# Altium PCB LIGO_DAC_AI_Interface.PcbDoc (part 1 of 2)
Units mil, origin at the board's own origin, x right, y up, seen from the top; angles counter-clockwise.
Board outline 2600 x 10000 mil, 6 copper layers (Top Layer, InternalPlane1, Mid-Layer 1, Mid-Layer 2, Internal Plane 2, Bottom Layer); 72 components, 113 nets, 425 pads, 169 vias.
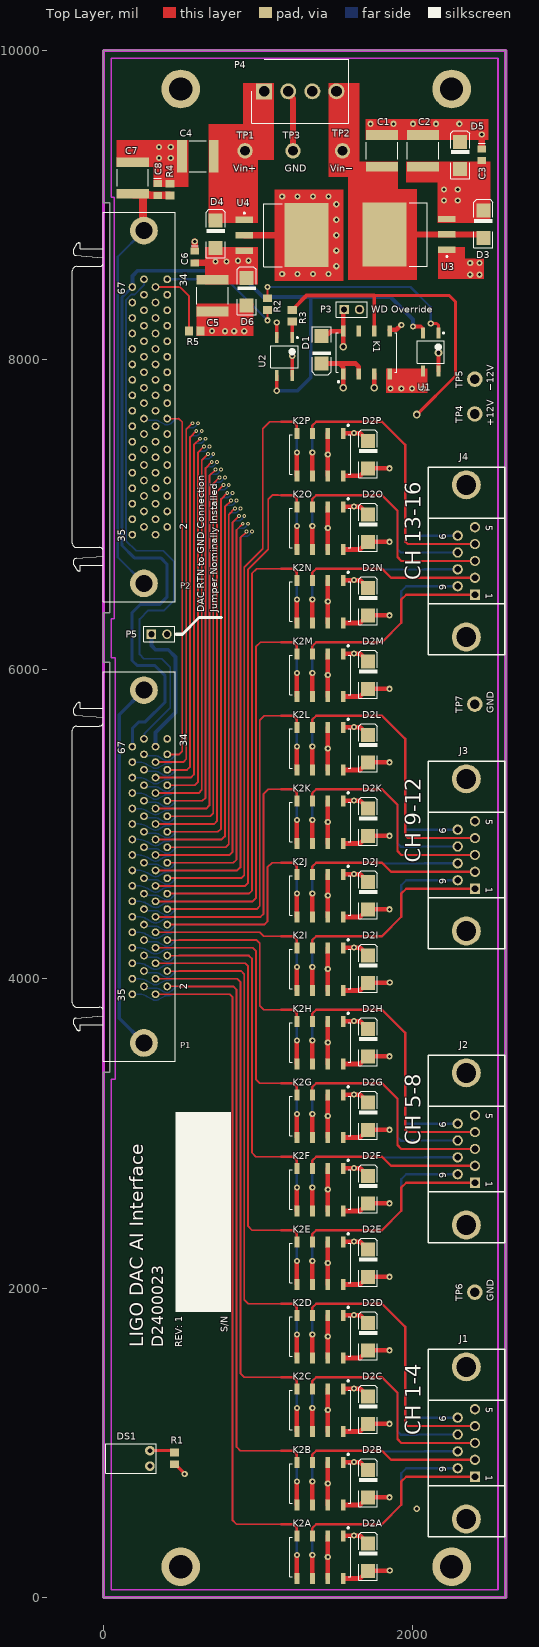
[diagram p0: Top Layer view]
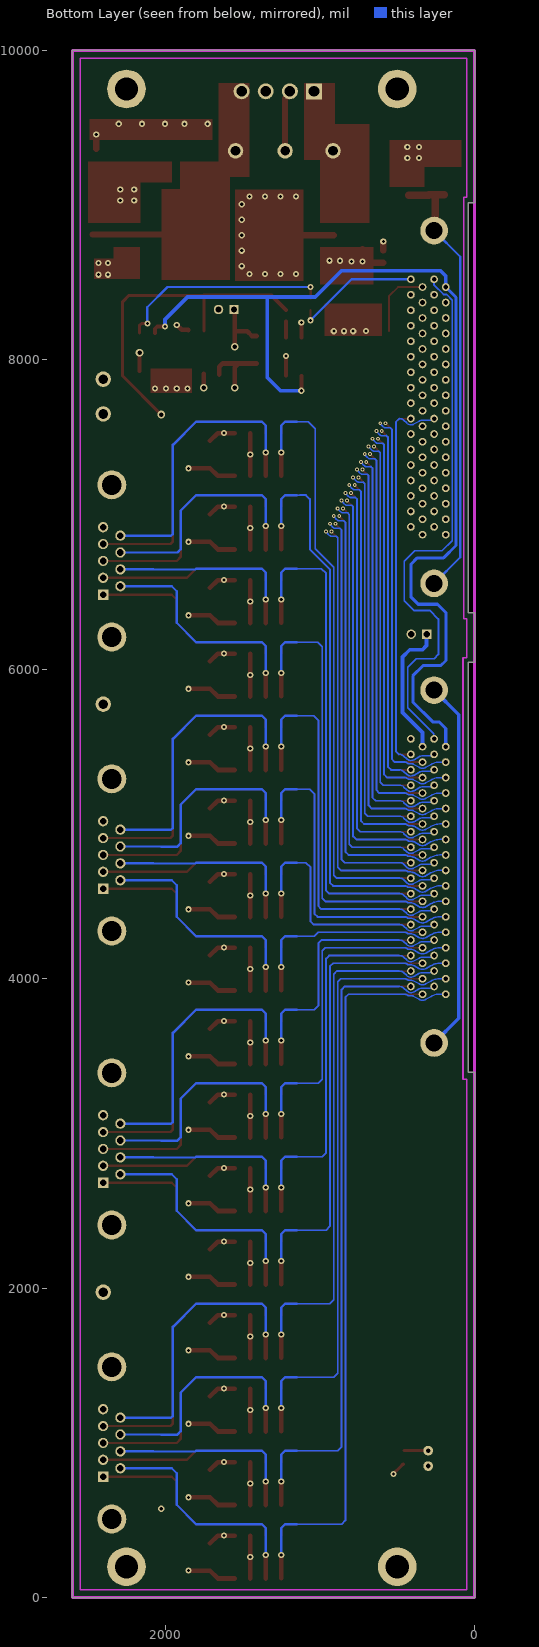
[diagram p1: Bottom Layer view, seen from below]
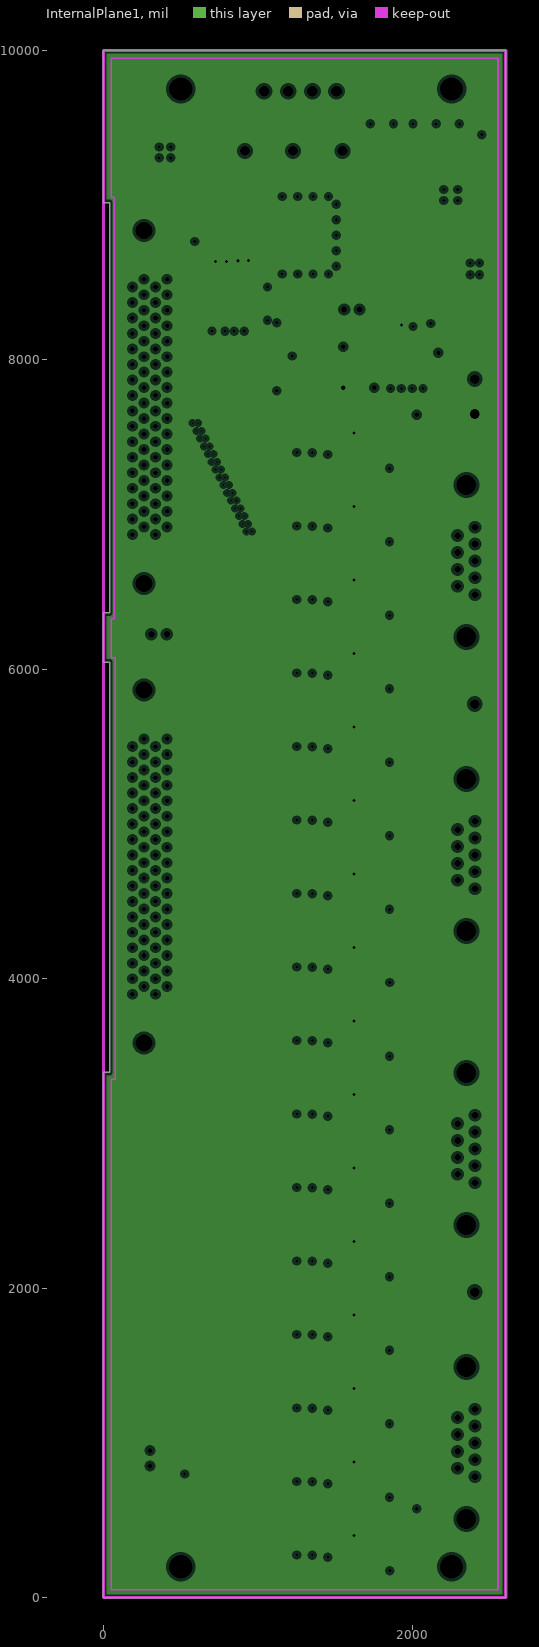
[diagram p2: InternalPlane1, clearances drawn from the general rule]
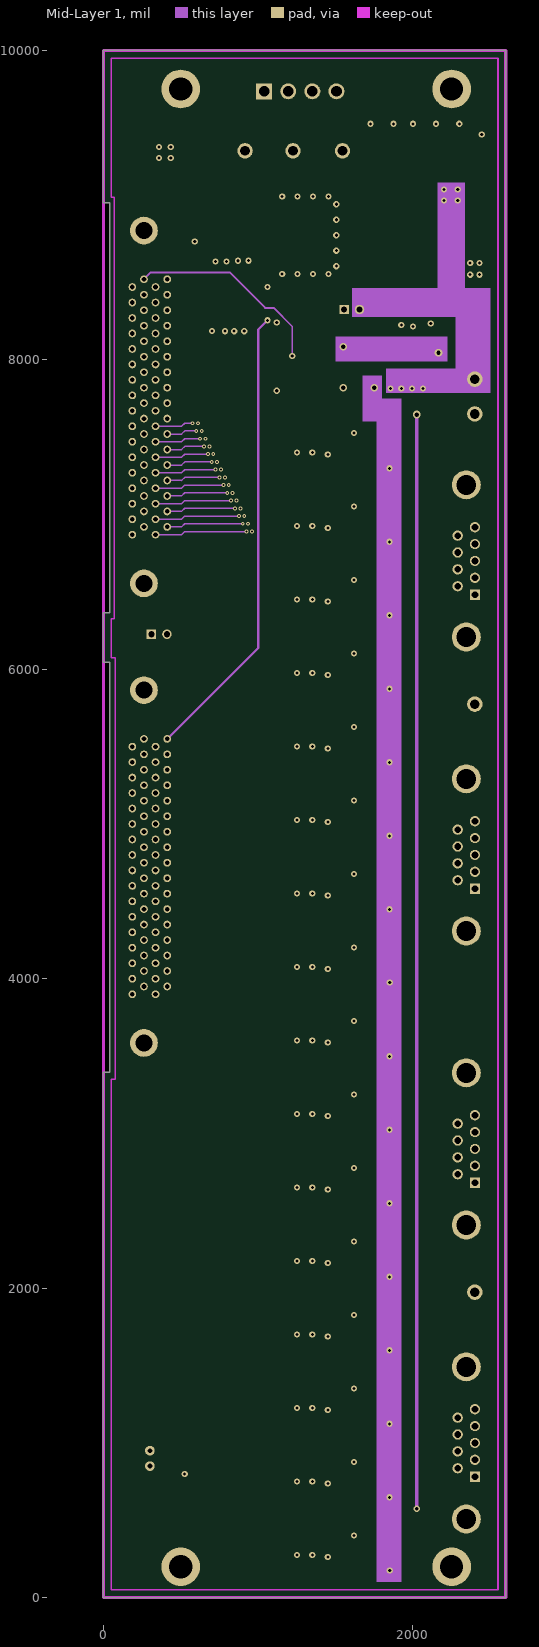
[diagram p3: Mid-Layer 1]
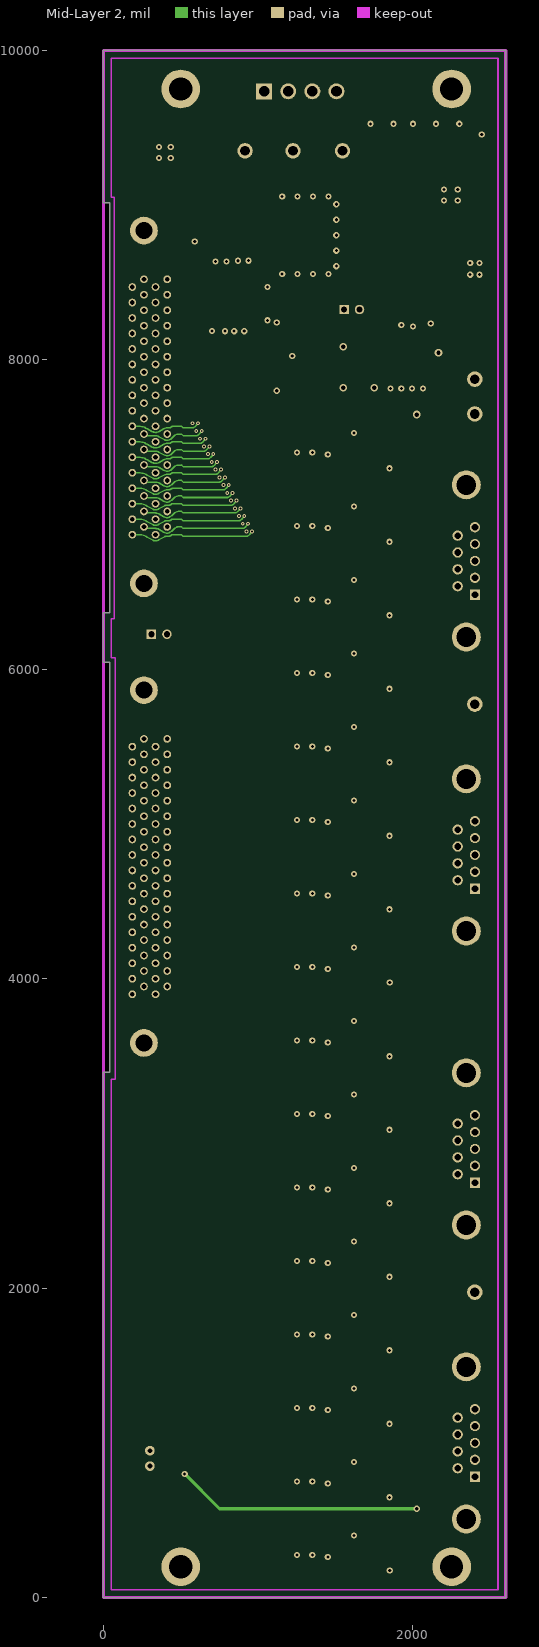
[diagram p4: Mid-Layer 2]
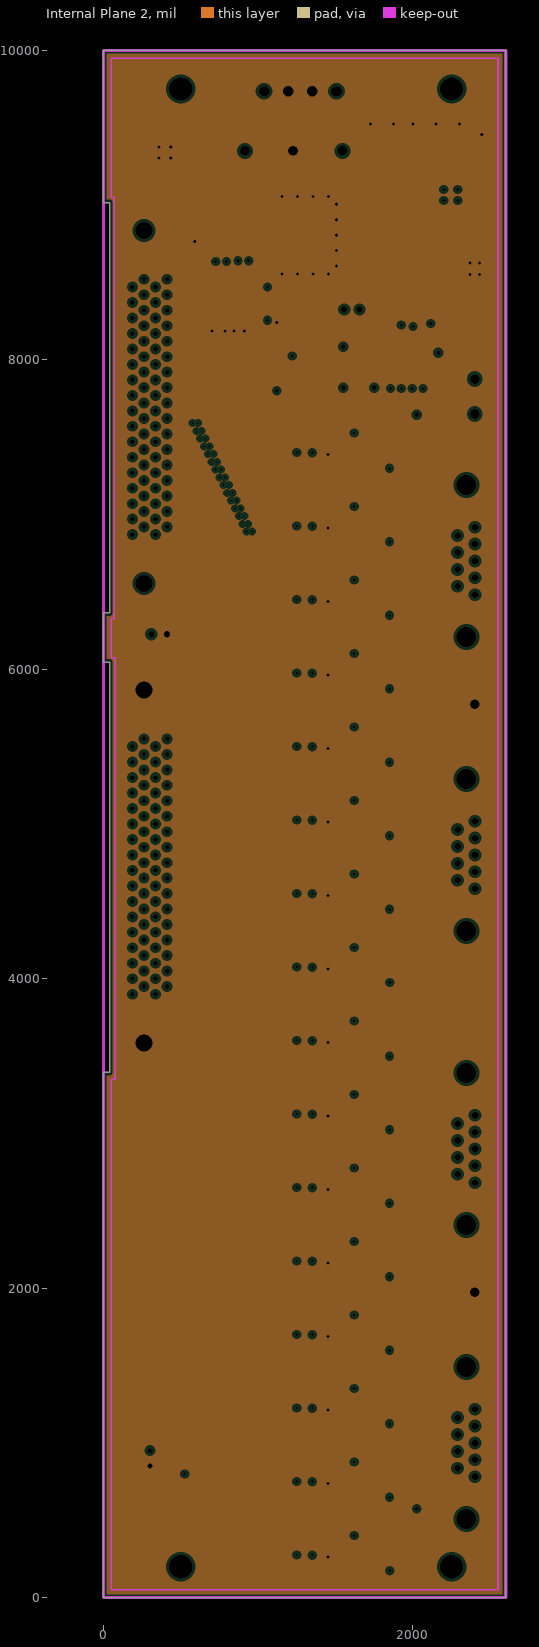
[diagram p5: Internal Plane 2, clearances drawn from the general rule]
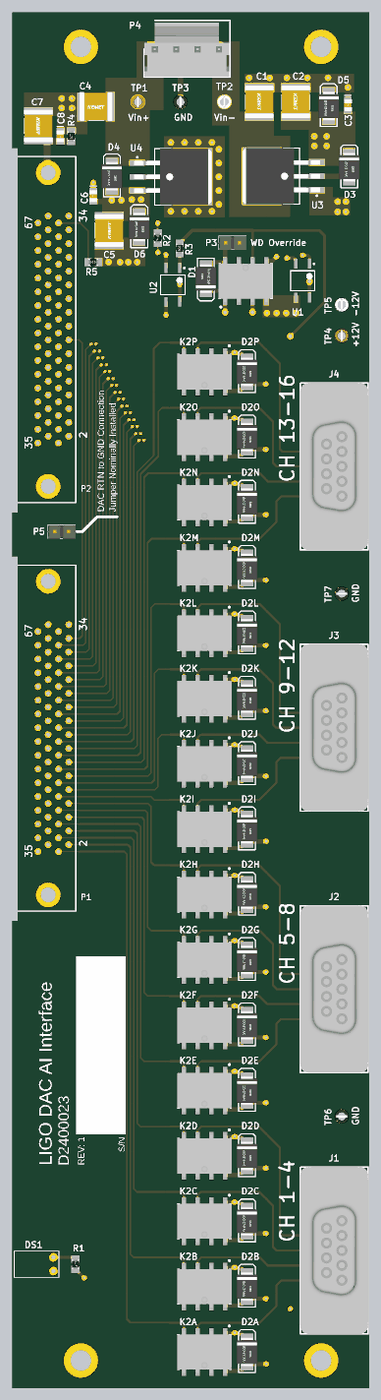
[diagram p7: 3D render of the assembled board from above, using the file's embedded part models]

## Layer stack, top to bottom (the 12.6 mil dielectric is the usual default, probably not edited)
Top Solder: solder mask 0.4, Solder Resist, Dk 3.5
Top Layer: signal copper 1.4
Dielectric1: core 12.6, FR-4, Dk 4.8
InternalPlane1: plane copper 1.4, net V+
Dielectric4: prepreg 12.6, FR-4, Dk 4.8
Mid-Layer 1: signal copper 1.4
Dielectric2: core 12.6, FR-4, Dk 4.8
Mid-Layer 2: signal copper 1.4
Dielectric3: prepreg 12.6, FR-4, Dk 4.8
Internal Plane 2: plane copper 1.4, net GND
Dielectric5: core 12.6, FR-4, Dk 4.8
Bottom Layer: signal copper 1.4
Bottom Solder: solder mask 0.4, Solder Resist, Dk 3.5

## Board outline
0,0 0,3395 40,3395 40,6045 0,6045 0,6365 40,6365 40,9015 0,9015 0,10000 2600,10000 2600,0

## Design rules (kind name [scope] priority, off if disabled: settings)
Clearance [All] p1: gap=10 ignorepadtopadclearanceinfootprint=FALSE
ComponentClearance ComponentClearance_1 [InComponent('P1')] p1: gap=0 collisioncheckmode=3 verticalgap=0 showdistances=FALSE
ComponentClearance ComponentClearance_2 [InComponent('P2')] p2: gap=0 collisioncheckmode=3 verticalgap=0 showdistances=FALSE
ComponentClearance ComponentClearance_3 [InComponent('DS1')] p3: gap=0 collisioncheckmode=3 verticalgap=0 showdistances=FALSE
ComponentClearance [All] p4: gap=10 collisioncheckmode=3 verticalgap=10 showdistances=FALSE
HoleSize [All] p1: absolutevalues=TRUE maxlimit=250 minlimit=12 maxpercent=80.000 minpercent=20.000
MinimumAnnularRing [All] p1: minimumring=6.5
PlaneClearance [All] p1: clearance=20
PlaneConnect [All] p1: planeconnectstyle=Relief reliefexpansion=20 reliefentries=4 reliefconductorwidth=10 reliefairgap=10
PolygonConnect [All] p1: connectstyle=Relief reliefconductorwidth=10 reliefentries=4 polygonreliefangle="90 Angle" airgapwidth=10
RoomDefinition Relay1 [InComponentClass('Relay1')] p1: confinementstyle=ConfineIn formatcopy=FALSE lockcomponents=FALSE outline 1150,50 1800,50 1800,525 1150,525
RoomDefinition Relay2 [InComponentClass('Relay2')] p2: confinementstyle=ConfineIn formatcopy=TRUE lockcomponents=FALSE outline 1150,525 1800,525 1800,1000 1150,1000
RoomDefinition Relay3 [InComponentClass('Relay3')] p3: confinementstyle=ConfineIn formatcopy=TRUE lockcomponents=FALSE outline 1150,1000 1800,1000 1800,1475 1150,1475
RoomDefinition Relay4 [InComponentClass('Relay4')] p4: confinementstyle=ConfineIn formatcopy=TRUE lockcomponents=FALSE outline 1150,1475 1800,1475 1800,1950 1150,1950
RoomDefinition Relay5 [InComponentClass('Relay5')] p5: confinementstyle=ConfineIn formatcopy=TRUE lockcomponents=FALSE outline 1150,1950 1800,1950 1800,2425 1150,2425
RoomDefinition Relay6 [InComponentClass('Relay6')] p6: confinementstyle=ConfineIn formatcopy=TRUE lockcomponents=FALSE outline 1150,2425 1800,2425 1800,2900 1150,2900
RoomDefinition Relay7 [InComponentClass('Relay7')] p7: confinementstyle=ConfineIn formatcopy=TRUE lockcomponents=FALSE outline 1150,2900 1800,2900 1800,3375 1150,3375
RoomDefinition Relay8 [InComponentClass('Relay8')] p8: confinementstyle=ConfineIn formatcopy=TRUE lockcomponents=FALSE outline 1150,3375 1800,3375 1800,3850 1150,3850
RoomDefinition Relay9 [InComponentClass('Relay9')] p9: confinementstyle=ConfineIn formatcopy=TRUE lockcomponents=FALSE outline 1150,3850 1800,3850 1800,4325 1150,4325
RoomDefinition Relay10 [InComponentClass('Relay10')] p10: confinementstyle=ConfineIn formatcopy=TRUE lockcomponents=FALSE outline 1150,4325 1800,4325 1800,4800 1150,4800
RoomDefinition Relay11 [InComponentClass('Relay11')] p11: confinementstyle=ConfineIn formatcopy=TRUE lockcomponents=FALSE outline 1150,4800 1800,4800 1800,5275 1150,5275
RoomDefinition Relay12 [InComponentClass('Relay12')] p12: confinementstyle=ConfineIn formatcopy=TRUE lockcomponents=FALSE outline 1150,5275 1800,5275 1800,5750 1150,5750
RoomDefinition Relay13 [InComponentClass('Relay13')] p13: confinementstyle=ConfineIn formatcopy=TRUE lockcomponents=FALSE outline 1150,5750 1800,5750 1800,6225 1150,6225
RoomDefinition Relay14 [InComponentClass('Relay14')] p14: confinementstyle=ConfineIn formatcopy=TRUE lockcomponents=FALSE outline 1150,6225 1800,6225 1800,6700 1150,6700
RoomDefinition Relay15 [InComponentClass('Relay15')] p15: confinementstyle=ConfineIn formatcopy=TRUE lockcomponents=FALSE outline 1150,6700 1800,6700 1800,7175 1150,7175
RoomDefinition Relay16 [InComponentClass('Relay16')] p16: confinementstyle=ConfineIn formatcopy=TRUE lockcomponents=FALSE outline 1150,7175 1800,7175 1800,7650 1150,7650
RoutingVias [All] p1: holewidth=20 width=40 viastyle="Through Hole" minholewidth=12 minwidth=25 maxholewidth=28 maxwidth=50
SilkToSolderMaskClearance SilkscreenOverComponentPads [IsPad] p1: minsilkscreentomaskgap=5 clearancetoexposedcopper=TRUE
SolderMaskExpansion SolderMaskExpansion_1 [IsVia And (HoleDiameter = 12)] p1: expansion=5 istentingtop=FALSE
SolderMaskExpansion [All] p2: expansion=4 istentingtop=FALSE
SupplyNets "Schematic Supply Nets_5" [InNet('V-')] p1: voltage=0.000
SupplyNets "Schematic Supply Nets_4" [InNet('DGND')] p2: voltage=0.000
SupplyNets "Schematic Supply Nets_3" [InNet('Vin+')] p3: voltage=0.000
SupplyNets "Schematic Supply Nets_2" [InNet('GND')] p4: voltage=0.000
SupplyNets "Schematic Supply Nets_1" [InNet('Vin-')] p5: voltage=0.000
SupplyNets "Schematic Supply Nets" [InNet('V+')] p6: voltage=0.000
Width [All] p1: maxlimit=100 minlimit=8 preferedwidth=12
25 further rules are at their usual default settings.

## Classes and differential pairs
net class OutputP[1..16]: OutputP1 OutputP2 OutputP3 OutputP4 OutputP5 OutputP6 OutputP7 OutputP8 OutputP9 OutputP10 OutputP11 OutputP12 OutputP13 OutputP14 OutputP15 OutputP16
net class OutputN[1..16]: OutputN1 OutputN2 OutputN3 OutputN4 OutputN5 OutputN6 OutputN7 OutputN8 OutputN9 OutputN10 OutputN11 OutputN12 OutputN13 OutputN14 OutputN15 OutputN16
channel class LIGO_DAC_AI_Interface2: Relay1 Relay2 Relay3 Relay4 Relay5 Relay6 Relay7 Relay8 Relay9 Relay10 Relay11 Relay12 Relay13 Relay14 Relay15 Relay16
net class INPUTP[1..16]: InputP1 InputP2 InputP3 InputP4 InputP5 InputP6 InputP7 InputP8 InputP9 InputP10 InputP11 InputP12 InputP13 INPUTP14 InputP15 InputP16
net class INPUTN[1..16]: InputN1 InputN2 InputN3 InputN4 InputN5 InputN6 InputN7 InputN8 InputN9 InputN10 InputN11 InputN12 InputN13 InputN14 InputN15 InputN16
component class Relay16: D2P K2P
component class Relay15: D2O K2O
component class Relay14: D2N K2N
component class Relay13: D2M K2M
component class Relay12: D2L K2L
component class Relay11: D2K K2K
component class Relay10: D2J K2J
component class Relay9: D2I K2I
component class Relay8: D2H K2H
component class Relay7: D2G K2G
component class Relay6: D2F K2F
component class Relay5: D2E K2E
component class Relay4: D2D K2D
component class Relay3: D2C K2C
component class Relay2: D2B K2B
component class Relay1: D2A K2A
component class LIGO_DAC_AI_Interface1: C1 C2 C3 C4 C5 C6 C7 C8 D1 D3 D4 D5 D6 DS1 J1 J2 J3 J4 K1 P1 P2 P3 P4 P5 R1 R2 R3 R4 R5 R6 TP1 TP2 TP3 TP4 TP5 TP6 TP7 U1 U2 U3 U4

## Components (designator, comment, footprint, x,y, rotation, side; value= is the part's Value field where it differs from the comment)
C1 "47u" CC5650-2220 1800,9350 r270 top
C2 "47u" CC5650-2220 2065,9350 r270 top
C3 "100n" CC2013-0805 2445,9325 r270 top
C4 "47u" CC5650-2220 610,9315 r0 top
C5 "47u" CC5650-2220 705,8415 r90 top
C6 "100n" CC2013-0805 590,8665 r270 top
C7 "47u" CC5650-2220 190,9175 r270 top
C8 "100n" CC2013-0805 350,9100 r270 top
D1 "RS2G" DO-SMB 1410,8065 r270 top
D2A "RS2G" DO-SMB 1710,262.2 r90 top (schematic designator D2)
D2B "RS2G" DO-SMB 1710,737.2 r90 top (schematic designator D2)
D2C "RS2G" DO-SMB 1710,1212.2 r90 top (schematic designator D2)
D2D "RS2G" DO-SMB 1710,1687.2 r90 top (schematic designator D2)
D2E "RS2G" DO-SMB 1710,2162.2 r90 top (schematic designator D2)
D2F "RS2G" DO-SMB 1710,2637.2 r90 top (schematic designator D2)
D2G "RS2G" DO-SMB 1710,3112.2 r90 top (schematic designator D2)
D2H "RS2G" DO-SMB 1710,3587.2 r90 top (schematic designator D2)
D2I "RS2G" DO-SMB 1710,4062.2 r90 top (schematic designator D2)
D2J "RS2G" DO-SMB 1710,4537.2 r90 top (schematic designator D2)
D2K "RS2G" DO-SMB 1710,5012.2 r90 top (schematic designator D2)
D2L "RS2G" DO-SMB 1710,5487.2 r90 top (schematic designator D2)
D2M "RS2G" DO-SMB 1710,5962.2 r90 top (schematic designator D2)
D2N "RS2G" DO-SMB 1710,6437.2 r90 top (schematic designator D2)
D2O "RS2G" DO-SMB 1710,6912.2 r90 top (schematic designator D2)
D2P "RS2G" DO-SMB 1710,7387.2 r90 top (schematic designator D2)
D3 "RS2G" DO-SMB 2455,8875 r90 top
D4 "RS2G" DO-SMB 725,8810 r90 top
D5 "RS2G" DO-SMB 2305,9320 r90 top
D6 "RS2G" DO-SMB 925,8440 r90 top
DS1 "LED" LED-1 300,900 r180 top
J1 "DB9F" DB9F-ST 2345,1000 r270 top locked
J2 "DB9F" DB9F-ST 2345,2900 r270 top locked
J3 "DB9F" DB9F-ST 2345,4800 r270 top
J4 "DB9F" DB9F-ST 2345,6700 r270 top locked
K1 "G6K" RELAY_G6K-2F 1700,8047.2 r270 top
K2A "G6K" RELAY_G6K-2F 1400,262.2 r90 top (schematic designator K2)
K2B "G6K" RELAY_G6K-2F 1400,737.2 r90 top (schematic designator K2)
K2C "G6K" RELAY_G6K-2F 1400,1212.2 r90 top (schematic designator K2)
K2D "G6K" RELAY_G6K-2F 1400,1687.2 r90 top (schematic designator K2)
K2E "G6K" RELAY_G6K-2F 1400,2162.2 r90 top (schematic designator K2)
K2F "G6K" RELAY_G6K-2F 1400,2637.2 r90 top (schematic designator K2)
K2G "G6K" RELAY_G6K-2F 1400,3112.2 r90 top (schematic designator K2)
K2H "G6K" RELAY_G6K-2F 1400,3587.2 r90 top (schematic designator K2)
K2I "G6K" RELAY_G6K-2F 1400,4062.2 r90 top (schematic designator K2)
K2J "G6K" RELAY_G6K-2F 1400,4537.2 r90 top (schematic designator K2)
K2K "G6K" RELAY_G6K-2F 1400,5012.2 r90 top (schematic designator K2)
K2L "G6K" RELAY_G6K-2F 1400,5487.2 r90 top (schematic designator K2)
K2M "G6K" RELAY_G6K-2F 1400,5962.2 r90 top (schematic designator K2)
K2N "G6K" RELAY_G6K-2F 1400,6437.2 r90 top (schematic designator K2)
K2O "G6K" RELAY_G6K-2F 1400,6912.2 r90 top (schematic designator K2)
K2P "G6K" RELAY_G6K-2F 1400,7387.2 r90 top (schematic designator K2)
P1 "787082-7" 787082-7 0,4725 r90 top locked
P2 "787082-7" 787082-7 0,7695 r90 top locked
P3 "Header 2" TSW-102-XX-YY-S 1555,8325 r0 top
P4 "26-61-4040" HDRV4W155P0X396_1X4_1570X1001X1536P 1038.19,9735 r180 top
P5 "Header 2" TSW-102-XX-YY-S 310,6226.5 r0 top
R1 "2.21K" CR2012-0805 460,900 r270 top
R2 "499" CR2012-0805 1060,8360 r90 top
R3 "2.21K" CR2012-0805 1220,8285 r90 top
R4 "NL" CR2012-0805 430,9100 r90 top
R5 "NL" CR2012-0805 590,8185 r0 top
TP1 "Vin+" TP1-RED 915,9350 r0 top
TP2 "Vin−" TP1-WHT 1545,9350 r0 top
TP3 "GND" TP1-BLK 1225,9350 r0 top
TP4 "+12V" TP1-RED 2400,7650 r180 top
TP5 "−12V" TP1-WHT 2400,7875 r180 top
TP6 "GND" TP1-BLK 2400,1975 r270 top
TP7 "GND" TP1-BLK 2400,5775 r270 top
U1 "PS2702-1-F3-A" PS2701A-1 2115,8050 r270 top
U2 "PS2702-1-F3-A" PS2701A-1 1170,8020 r270 top
U3 "LM2990SX-12/NOPB" KTT0003B_N 1975,8810 r180 top
U4 "LM2940CSX-12/NOPB" KTT0003B_N 1155,8805 r0 top

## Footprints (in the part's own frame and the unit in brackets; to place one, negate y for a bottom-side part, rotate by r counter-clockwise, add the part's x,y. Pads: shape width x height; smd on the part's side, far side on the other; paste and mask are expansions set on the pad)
787082-7 [mm] "Connector; D Subminiature 050 Series; 68 Position; Right Angle"
  round 1.27 hole 0.762: 1(-20.955,-8.555) 2(-19.685,-10.46) 3(-18.415,-8.555) 4(-17.145,-10.46) 5(-15.875,-8.555) 6(-14.605,-10.46) 7(-13.335,-8.555) 8(-12.065,-10.46) 9(-10.795,-8.555) 10(-9.525,-10.46) 11(-8.255,-8.555) 12(-6.985,-10.46) 13(-5.715,-8.555) 14(-4.445,-10.46) 15(-3.175,-8.555) 16(-1.905,-10.46) 17(-0.635,-8.555) 18(0.635,-10.46) 19(1.905,-8.555) 20(3.175,-10.46) 21(4.445,-8.555) 22(5.715,-10.46) 23(6.985,-8.555) 24(8.255,-10.46) 25(9.525,-8.555) 26(10.795,-10.46) 27(12.065,-8.555) 28(13.335,-10.46) 29(14.605,-8.555) 30(15.875,-10.46) 31(17.145,-8.555) 32(18.415,-10.46) 33(19.685,-8.555) 34(20.955,-10.46) 35(-20.955,-4.745) 36(-19.685,-6.65) 37(-18.415,-4.745) 38(-17.145,-6.65) 39(-15.875,-4.745) 40(-14.605,-6.65) 41(-13.335,-4.745) 42(-12.065,-6.65) 43(-10.795,-4.745) 44(-9.525,-6.65) 45(-8.255,-4.745) 46(-6.985,-6.65) 47(-5.715,-4.745) 48(-4.445,-6.65) 49(-3.175,-4.745) 50(-1.905,-6.65) 51(-0.635,-4.745) 52(0.635,-6.65) 53(1.905,-4.745) 54(3.175,-6.65) 55(4.445,-4.745) 56(5.715,-6.65) 57(6.985,-4.745) 58(8.255,-6.65) 59(9.525,-4.745) 60(10.795,-6.65) 61(12.065,-4.745) 62(13.335,-6.65) 63(14.605,-4.745) 64(15.875,-6.65) 65(17.145,-4.745) 66(18.415,-6.65) 67(19.685,-4.745) 68(20.955,-6.65)
  round 4.55 hole 2.77: 69(-28.955,-6.65) 70(28.955,-6.65)
  silkscreen extent -31.95,-11.76 31.95,5.11
CC2013-0805 [mm] "Chip Capacitor; Body 2.0 x 1.3 mm (LxW typ)"
  rect 1.15x1.4 smd: 1(-0.975,0) 2(0.975,0)
  silkscreen extent -1.85,-0.6 -1.85,0.6, body extent -1.1,-0.72 1.1,0.73, height 0.88
CC5650-2220 [mm] "Chip Capacitor, Body 5.6 x 5.0mm (LxW typ)"
  rect 1.6x5.3 smd: 1(-2.6,0) 2(2.6,0)
  silkscreen extent -1.4,-2.55 1.4,2.55, body extent -3.05,-2.7 3.05,2.7, height 1.8
CR2012-0805 [mm] "Chip Resistor; Body 2.0 x 1.3 mm (LxW typ)"
  rect 1.3x1.5 smd: 1(-0.95,0) 2(0.95,0)
  body extent -1,-0.62 1,0.63, height 0.46
DB9F-ST [mm] "Receptiacle; D Subminiature 9 Position; Straight"
  rect 1.69x1.69 hole 1.09: 1(5.54,1.42)
  round 1.69 hole 1.09: 2(2.77,1.42) 3(0,1.42) 4(-2.77,1.42) 5(-5.54,1.42) 6(4.155,-1.42) 7(1.385,-1.42) 8(-1.385,-1.42) 9(-4.155,-1.42)
  round 4.76 hole 3.26: 10(12.495,0) 11(-12.495,0)
  silkscreen extent -15.4,-6.27 15.4,6.27, body extent -15.44,-6.3 15.44,6.3, height 12.32
DO-SMB [mm] "DO-214-AA/SMB; 2 C-Bend Leads; Body 5.3 x 3.6 mm, inc. leads (LxW)"
  rect 2.3x2.3 smd: 1(-2.25,0) 2(2.25,0)
  silkscreen extent -3.8,-1.55 4.1,1.55, body extent -2.75,-1.95 2.75,1.95, height 2.45
HDRV4W155P0X396_1X4_1570X1001X1536P [mm]
  rect 2.625x2.625 hole 1.75: 1(0,0)
  round 2.625 hole 1.75: 2(-3.96,0) 3(-7.92,0) 4(-11.88,0)
  silkscreen extent -13.91,-5.26 2.03,5.26, body extent -13.79,-4.83 1.91,5.17, height 14.73
KTT0003B_N [mm]
  rect 2.85x1.05 smd: 1(-6.2,2.54) 2(-6.2,0) 3(-6.2,-2.54)
  rect 7.2x10.5 smd: 4(4,0)
  silkscreen extent -6.33,-5.2 0,5.2, body extent -6.78,-5.2 7.57,5.2, height 4.64
LED-1 [mm] "Typical RED GaAs LED; 2 Leads"
  round 1.6 hole 0.8: 1(0,1.27) 2(0,-1.27)
  silkscreen extent -1.02,-2.41 7.24,2.41
PS2701A-1 [mm] "SOP, 4-Leads, Body 4.5x4.4mm (max), Pitch 2.54mm, IPC Medium Density"
  rect 1.8x0.6 smd: 1(-3.125,1.27) 2(-3.125,-1.27) 3(3.125,-1.27) 4(3.125,1.27)
  silkscreen extent -3.25,-2.25 1.83,2.25, body extent -2.2,-2.25 2.2,2.25, height 2.3
RELAY_G6K-2F [mm] "Relay"
  rect 1.8x0.8 smd: 1(3.5,-3.81) 2(3.5,-1.27) 3(3.5,1.27) 4(3.5,3.81) 5(-3.5,3.81) 6(-3.5,1.27) 7(-3.5,-1.27) 8(-3.5,-3.81)
  silkscreen extent -3.25,-5 4.94,5, body extent -3.9,-5 3.9,5, height 5.2
TP1-BLK [mm] "Testpoint pin, black"
  round 2.54 hole 1.58: 1(0,0)
  body extent -1.27,-1.27 1.27,1.27, height 4.89
TP1-RED [mm] "Testpoint pin, red"
  round 2.54 hole 1.58: 1(0,0)
  body extent -1.27,-1.27 1.27,1.27, height 4.89
TP1-WHT [mm] "Testpoint pin, white"
  round 2.54 hole 1.58: 1(0,0)
  body extent -1.27,-1.27 1.27,1.27, height 4.89
TSW-102-XX-YY-S [mm]
  rect 1.55x1.55 hole 1.02: 1(0,0)
  round 1.55 hole 1.02: 2(2.54,0)
  silkscreen extent -1.27,-1.27 3.81,1.27, body extent -1.39,-1.28 3.82,1.26, height 9.16

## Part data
C1 C2 C4 C5 C7: library part ChipCap, "Capacitor, surface mount", Part Number=445-C5750X7R1V476M230KCCT-ND, Tolerance=10%, Voltage Rating=35V
C3 C6 C8: library part ChipCap, "Capacitor, surface mount", Part Number=311-1140-1-ND, Tolerance=10%
D1 D2A D2B D2C D2D D2E D2F D2G D2H D2I D2J D2K D2L D2M D2N D2O D2P D3 D4 D5 D6: library part DIODE, "Single diode", Part Number=RS2G-E3/52TGICT-ND, Voltage Rating=400V
DS1: "Panel mount LED", Part Number=67-1304-ND
J1 J2 J3 J4: "Receptacle Assembly, 9 Position, Right Angle, .318 Series", Part Number=A34072-ND
K1 K2A K2B K2C K2D K2E K2F K2G K2H K2I K2J K2K K2L K2M K2N K2O K2P: library part Relay_DPDT_GK, "Dual-pole dual-throw relay", Coil Voltage=24V, Current Rating=2A, Part Number=Z114CT-ND
P1 P2: "Receptacle Assembly, Shielded, Right Angle, AMPLIMITE", Part Number=A31814-ND
P3 P5: "Header, 2-Pin", Part Number=SAM10844-ND
P4: "Connector", Manufacturer_Name=Molex, Part Number=WM5226-ND
R1 R3: library part ChipRes1, "Resistor, surface mount", Part Number=311-2.21KCRCT-ND, Tolerance=1%
R2: library part ChipRes1, "Resistor, surface mount", Part Number=311-499CRCT-ND, Tolerance=1%
R4 R5: library part ChipRes1, "Resistor, surface mount", Tolerance=1%
TP1 TP4: library part TP_POSITIVE, "Testpoint, red", Part Number=5005K-ND
TP2 TP5: library part TP_NEGATIVE, "Testpoint, white", Part Number=5007K-ND
TP3 TP6 TP7: library part TP_GND, "Testpoint, black", Part Number=5006K-ND
U1 U2: library part PS2701A, "High Isolation Voltage SOP Photocoupler", Part Number=559-1027-1-ND
U3: library part LM2990SX-12, "Negative Low Dropout Regulator, 3-pin TO-263", Part Number=LM2990SX-12/NOPBCT-ND
U4: library part LM2940CS-12/NOPB, "1A Low Dropout Regulator, 3-pin TO-263, Pb-Free", Part Number=LM2940CSX-12/NOPBCT-ND

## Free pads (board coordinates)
  round 250 hole 150: 0(2250,200) 1(2250,9750) 2(500,9750) 3(500,200)

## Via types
v1: diameter 40, hole 20, Top Layer to Bottom Layer, 134 vias
v2: diameter 25, hole 12, Top Layer to Bottom Layer, 30 vias
v3: diameter 50, hole 28, Top Layer to Bottom Layer, 5 vias

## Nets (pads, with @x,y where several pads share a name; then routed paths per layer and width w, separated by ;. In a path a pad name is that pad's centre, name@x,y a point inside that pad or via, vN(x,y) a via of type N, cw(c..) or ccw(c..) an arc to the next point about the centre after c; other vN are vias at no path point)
DAC1ENABLE: D2A.1 D2B.1 D2C.1 D2D.1 D2E.1 D2F.1 D2G.1 D2H.1 D2I.1 D2J.1 D2K.1 D2L.1 D2M.1 D2N.1 D2O.1 D2P.1 K1.3 K2A.8 K2B.8 K2C.8 K2D.8 K2E.8 K2F.8 K2G.8 K2H.8 K2I.8 K2J.8 K2K.8 K2L.8 K2M.8 K2N.8 K2O.8 K2P.8 | length 5195.5
  Top Layer w30: K2A.8@1550,124.41 1660.79,124.41 D2A.1@1710,173.62 1848.62,173.62 v1(1850,175) ; K2B.8@1550,599.41 1660.79,599.41 D2B.1@1710,648.62 v1(1848.62,648.62) ; K2C.8@1550,1074.41 1660.79,1074.41 D2C.1@1710,1123.62 v1(1848.62,1123.62) ; K2D.8@1550,1549.41 1660.79,1549.41 D2D.1@1710,1598.62 v1(1848.62,1598.62) ; K2E.8@1550,2024.41 1660.79,2024.41 D2E.1@1710,2073.62 v1(1848.62,2073.62) ; K2F.8@1550,2499.41 1660.79,2499.41 D2F.1@1710,2548.62 v1(1848.62,2548.62) ; K2G.8@1550,2974.41 1660.79,2974.41 D2G.1@1710,3023.62 v1(1848.62,3023.62) ; K2H.8@1550,3449.41 1660.79,3449.41 D2H.1@1710,3498.62 v1(1848.62,3498.62) ; K2I.8@1550,3924.41 1660.79,3924.41 D2I.1@1710,3973.62 v1@1848.62,3973.62 ; K2J.8@1550,4399.41 1660.79,4399.41 D2J.1@1710,4448.62 v1(1848.62,4448.62) ; K2K.8@1550,4874.41 1660.79,4874.41 D2K.1@1710,4923.62 v1(1848.62,4923.62) ; K2L.8@1550,5349.41 1660.79,5349.41 D2L.1@1710,5398.62 v1(1848.62,5398.62) ; K2M.8@1550,5824.41 1660.79,5824.41 D2M.1@1710,5873.62 v1(1848.62,5873.62) ; K2N.8@1550,6299.41 1660.79,6299.41 D2N.1@1710,6348.62 v1(1848.62,6348.62) ; K2O.8@1550,6774.41 1660.79,6774.41 D2O.1@1710,6823.62 v1(1848.62,6823.62) ; K2P.8@1550,7249.41 1660.79,7249.41 D2P.1@1710,7298.62 v1(1848.62,7298.62) ; v3(1750,7820) K1.3@1750,7909.41
  other v1: 1850,3975
DGND: P1.67 P2.67 U1.2 U2.3 | length 6695.9
  Top Layer w25: v1(1120,7800) U2.3@1120,7896.97 ; v1(2000,8215) 2050.36,8215 2065,8200.36 U1.2@2065,8173.03
  Bottom Layer w18: 120,6800 120,8403.19
  Bottom Layer w20: 120,6800 200,6720 370,6720 410,6680 410,6465 365,6420 240,6420 185,6365 185,6057 218,6024 332,6024 399,5957 399,5788 271,5660 230,5660 186.81,5616.81 P1.67@186.81,5500 ; 120,8403.19 P2.67@186.81,8470
  Bottom Layer w25: P2.67@186.81,8470 186.81,8541.81 220,8575 860,8575 1030,8405 1340,8405 ; v1(1120,7800) 1255,7800 1340,7885 1340,8405 ; v1(2000,8215) 2000,8260 1855,8405 1340,8405
GND: C1.1 C2.1 C3.1 C4.1 C5.1 C6.1 C7.1 C8.1 D5.2 D6.1 DS1.1 K2A.2 K2A.7 K2B.2 K2B.7 K2C.2 K2C.7 K2D.2 K2D.7 K2E.2 K2E.7 K2F.2 K2F.7 K2G.2 K2G.7 K2H.2 K2H.7 K2I.2 K2I.7 K2J.2 K2J.7 K2K.2 K2K.7 K2L.2 K2L.7 K2M.2 K2M.7 K2N.2 K2N.7 K2O.2 K2O.7 K2P.2 K2P.7 P1.69 P1.70 P4.2 P4.3 P5.2 R4.2 R5.2 TP3.1 TP6.1 TP7.1 U2.2 U3.1 U4.2 U4.4 | length 8010.7
  Top Layer w25: R5.2@624.4,8185.4 v1(702,8185.4) ; U2.2@1120,8143.03 v1(1120,8240)
  Top Layer w30: K2A.7@1450,124.41 v1(1450,262.2) K2A.2@1450,400 ; K2B.7@1450,599.41 v1(1450,737.2) K2B.2@1450,875 ; K2C.7@1450,1074.41 v1(1450,1212.2) K2C.2@1450,1350 ; K2D.7@1450,1549.41 v1(1450,1687.2) K2D.2@1450,1825 ; K2E.7@1450,2024.41 v1(1450,2162.2) K2E.2@1450,2300 ; K2F.7@1450,2499.41 v1(1450,2637.2) K2F.2@1450,2775 ; K2G.7@1450,2974.41 v1(1450,3112.2) K2G.2@1450,3250 ; K2H.7@1450,3449.41 v1(1450,3587.2) K2H.2@1450,3725 ; K2I.7@1450,3924.41 v1(1450,4062.2) K2I.2@1450,4200 ; K2J.7@1450,4399.41 v1(1450,4537.2) K2J.2@1450,4675 ; K2K.7@1450,4874.41 v1(1450,5012.2) K2K.2@1450,5150 ; K2L.7@1450,5349.41 v1(1450,5487.2) K2L.2@1450,5625 ; K2M.7@1450,5824.41 v1(1450,5962.2) K2M.2@1450,6100 ; K2N.7@1450,6299.41 v1(1450,6437.2) K2N.2@1450,6575 ; K2O.7@1450,6774.41 v1(1450,6912.2) K2O.2@1450,7050 ; K2P.7@1450,7249.41 v1(1450,7387.2) K2P.2@1450,7525
  Top Layer w40: C6.1@590,8706.02 v1(590,8765) ; U4.2@910.91,8805 U4.4@1312.48,8805 ; P4.2@1206,9725 1206,9705.95 1225,9686.95 TP3.1@1225,9350 TP3.1@1225,9344.27 ; C2.1@2040,9450.98 2040,9525 ; C3.1@2445,9363.39 v1(2445,9455)
  Bottom Layer w25: P1.69@261.81,3585.04 102.5,3744.35 102.5,5705.65 P1.70@261.81,5864.96
  other v1: 785,8185 845,8185 910,8185 2370,8550 2430,8550 1155,8555 1255,8555 1355,8555 1455,8555 1505,8605 2370,8625 2430,8625 1505,8705 1505,8805 1505,8905 1505,9005 1155,9055 1255,9055 1355,9055 1455,9055 360,9305 435,9305 360,9375 435,9375 1725,9525 1875,9525 2000,9525 2150,9525 2300,9525
InputN1: K2A.5 P1.35 | length 4815.4
  Top Layer w30: K2A.5@1250,125 v1(1250,275.59)
  Bottom Layer w9: P1.35@186.81,3900 224.74,3900 226.94,3900 cw(c226.94,3794.19) 283.01,3883.92 283.21,3883.81 315.61,3866.08 ccw(c336.81,3900) 336.81,3860 ccw(c336.81,3900) 358.01,3866.08 390.61,3883.92 cw(c411.81,3850) 411.81,3890 424.74,3890 ccw(c424.74,3907.07) 436.81,3895 cw(c448.88,3882.93) 448.88,3900 486.81,3900
  Bottom Layer w12: 486.81,3900 815,3900 835,3880 835,500 860,475 1130,475 1150,475
  Bottom Layer w15: 1150,475 1225,475 1250,450 v1(1250,275.59)
InputN2: K2B.5 P1.36 | length 4320
  Top Layer w30: K2B.5@1250,600 v1(1250,750.59)
  Bottom Layer w9: P1.36@261.81,3950 ccw(c285.95,3974.14) 285.95,3940 336.81,3940 cw(c336.81,3900) 358.01,3933.92 390.61,3916.08 ccw(c411.81,3950) 411.81,3910 ccw(c411.81,3950) 440.1,3921.72 440.1,3921.92 456.46,3938.28 cw(c484.74,3910) 484.74,3950 486.81,3950
  Bottom Layer w12: 486.81,3950 840,3950 860,3930 860,975 885,950 1130,950 1150,950
  Bottom Layer w15: 1150,950 1225,950 1250,925 v1(1250,750.59)
InputN3: K2C.5 P1.37 | length 3965.4
  Top Layer w30: K2C.5@1250,1075 v1(1250,1225.59)
  Bottom Layer w9: P1.37@186.81,4000 224.74,4000 226.94,4000 cw(c226.94,3894.19) 283.01,3983.92 283.21,3983.81 315.61,3966.08 ccw(c336.81,4000) 336.81,3960 ccw(c336.81,4000) 358.01,3966.08 390.61,3983.92 cw(c411.81,3950) 411.81,3990 424.74,3990 ccw(c424.74,4007.07) 436.81,3995 cw(c448.88,3982.93) 448.88,4000 486.81,4000
  Bottom Layer w12: 486.81,4000 865,4000 885,3980 885,1450 910,1425 1130,1425 1150,1425
  Bottom Layer w15: 1150,1425 1225,1425 1250,1400 v1(1250,1225.59)
InputN4: K2D.5 P1.38 | length 3470
  Top Layer w30: K2D.5@1250,1550 v1(1250,1700.59)
  Bottom Layer w9: P1.38@261.81,4050 ccw(c285.95,4074.14) 285.95,4040 336.81,4040 cw(c336.81,4000) 358.01,4033.92 390.61,4016.08 ccw(c411.81,4050) 411.81,4010 ccw(c411.81,4050) 440.1,4021.72 440.1,4021.92 456.46,4038.28 cw(c484.74,4010) 484.74,4050 486.81,4050
  Bottom Layer w12: 486.81,4050 890,4050 910,4030 910,1925 935,1900 1130,1900 1150,1900
  Bottom Layer w15: 1150,1900 1225,1900 1250,1875 v1(1250,1700.59)
InputN5: K2E.5 P1.39 | length 3115.4
  Top Layer w30: K2E.5@1250,2025 v1(1250,2175.59)
  Bottom Layer w9: P1.39@186.81,4100 224.74,4100 226.94,4100 cw(c226.94,3994.19) 283.01,4083.92 283.21,4083.81 315.61,4066.08 ccw(c336.81,4100) 336.81,4060 ccw(c336.81,4100) 358.01,4066.08 390.61,4083.92 cw(c411.81,4050) 411.81,4090 424.74,4090 ccw(c424.74,4107.07) 436.81,4095 cw(c448.88,4082.93) 448.88,4100 486.81,4100
  Bottom Layer w12: 486.81,4100 915,4100 935,4080 935,2400 960,2375 1130,2375 1150,2375
  Bottom Layer w15: 1150,2375 1225,2375 1250,2350 v1(1250,2175.59)
InputN6: K2F.5 P1.40 | length 2620
  Top Layer w30: K2F.5@1250,2500 v1(1250,2650.59)
  Bottom Layer w9: P1.40@261.81,4150 ccw(c285.95,4174.14) 285.95,4140 336.81,4140 cw(c336.81,4100) 358.01,4133.92 390.61,4116.08 ccw(c411.81,4150) 411.81,4110 ccw(c411.81,4150) 440.1,4121.72 440.1,4121.92 456.46,4138.28 cw(c484.74,4110) 484.74,4150 486.81,4150
  Bottom Layer w12: 486.81,4150 940,4150 960,4130 960,2875 985,2850 1130,2850 1150,2850
  Bottom Layer w15: 1150,2850 1225,2850 1250,2825 v1(1250,2650.59)
InputN7: K2G.5 P1.41 | length 2265.4
  Top Layer w30: K2G.5@1250,2975 v1(1250,3125.59)
  Bottom Layer w9: P1.41@186.81,4200 224.74,4200 226.94,4200 cw(c226.94,4094.19) 283.01,4183.92 283.21,4183.81 315.61,4166.08 ccw(c336.81,4200) 336.81,4160 ccw(c336.81,4200) 358.01,4166.08 390.61,4183.92 cw(c411.81,4150) 411.81,4190 424.74,4190 ccw(c424.74,4207.07) 436.81,4195 cw(c448.88,4182.93) 448.88,4200 486.81,4200
  Bottom Layer w12: 486.81,4200 965,4200 985,4180 985,3350 1010,3325 1130,3325 1150,3325
  Bottom Layer w15: 1150,3325 1225,3325 1250,3300 v1(1250,3125.59)
InputN8: K2H.5 P1.42 | length 1770
  Top Layer w30: K2H.5@1250,3450 v1(1250,3600.59)
  Bottom Layer w9: P1.42@261.81,4250 ccw(c285.95,4274.14) 285.95,4240 336.81,4240 cw(c336.81,4200) 358.01,4233.92 390.61,4216.08 ccw(c411.81,4250) 411.81,4210 ccw(c411.81,4250) 440.1,4221.72 440.1,4221.92 456.46,4238.28 cw(c484.74,4210) 484.74,4250 486.81,4250
  Bottom Layer w12: 486.81,4250 990,4250 1010,4230 1010,3825 1035,3800 1130,3800 1150,3800
  Bottom Layer w15: 1150,3800 1225,3800 1250,3775 v1(1250,3600.59)
InputN9: K2I.5 P1.43 | length 1427.2
  Top Layer w30: K2I.5@1250,3925 v1(1250,4075.59)
  Bottom Layer w9: P1.43@186.81,4300 224.74,4300 226.94,4300 cw(c226.94,4194.19) 283.01,4283.92 283.21,4283.81 315.61,4266.08 ccw(c336.81,4300) 336.81,4260 ccw(c336.81,4300) 358.01,4266.08 390.61,4283.92 cw(c411.81,4250) 411.81,4290 424.74,4290 ccw(c424.74,4307.07) 436.81,4295 cw(c448.88,4282.93) 448.88,4300 486.81,4300
  Bottom Layer w12: 486.81,4300 1010,4300 1035,4275 1130,4275 1150,4275
  Bottom Layer w15: 1150,4275 1225,4275 1250,4250 v1(1250,4075.59)
InputN10: K2J.5 P1.44 | length 1717
  Top Layer w30: K2J.5@1250,4400 v1(1250,4550.59)
  Bottom Layer w9: P1.44@261.81,4350 ccw(c285.95,4374.14) 285.95,4340 336.81,4340 cw(c336.81,4300) 358.01,4333.92 390.61,4316.08 ccw(c411.81,4350) 411.81,4310 ccw(c411.81,4350) 440.1,4321.72 440.1,4321.92 456.46,4338.28 cw(c484.74,4310) 484.74,4350
  Bottom Layer w12: 484.74,4350 1040,4350 1060,4370 1060,4720 1090,4750 1130,4750 1150,4750
  Bottom Layer w15: 1150,4750 1225,4750 1250,4725 v1(1250,4550.59)
InputN11: K2K.5 P1.45 | length 2212.5
  Top Layer w30: K2K.5@1250,4875 v1(1250,5025.59)
  Bottom Layer w9: P1.45@186.81,4400 224.74,4400 226.94,4400 cw(c226.94,4294.19) 283.01,4383.92 283.21,4383.81 315.61,4366.08 ccw(c336.81,4400) 336.81,4360 ccw(c336.81,4400) 358.01,4366.08 390.61,4383.92 cw(c411.81,4350) 411.81,4390 424.74,4390 ccw(c424.74,4407.07) 436.81,4395 cw(c448.88,4382.93) 448.88,4400
  Bottom Layer w12: 448.88,4400 1015,4400 1035,4420 1035,5195 1065,5225 1130,5225 1150,5225
  Bottom Layer w15: 1150,5225 1225,5225 1250,5200 v1(1250,5025.59)
InputN12: K2L.5 P1.46 | length 2567
  Top Layer w30: K2L.5@1250,5350 v1(1250,5500.59)
  Bottom Layer w9: P1.46@261.81,4450 ccw(c285.95,4474.14) 285.95,4440 336.81,4440 cw(c336.81,4400) 358.01,4433.92 390.61,4416.08 ccw(c411.81,4450) 411.81,4410 ccw(c411.81,4450) 440.1,4421.72 440.1,4421.92 456.46,4438.28 cw(c484.74,4410) 484.74,4450
  Bottom Layer w12: 484.74,4450 990,4450 1010,4470 1010,5670 1040,5700 1130,5700 1150,5700
  Bottom Layer w15: 1150,5700 1225,5700 1250,5675 v1(1250,5500.59)
InputN13: K2M.5 P1.47 | length 3062.5
  Top Layer w30: K2M.5@1250,5825 v1(1250,5975.59)
  Bottom Layer w9: P1.47@186.81,4500 224.74,4500 226.94,4500 cw(c226.94,4394.19) 283.01,4483.92 283.21,4483.81 315.61,4466.08 ccw(c336.81,4500) 336.81,4460 ccw(c336.81,4500) 358.01,4466.08 390.61,4483.92 cw(c411.81,4450) 411.81,4490 424.74,4490 ccw(c424.74,4507.07) 436.81,4495 cw(c448.88,4482.93) 448.88,4500
  Bottom Layer w12: 448.88,4500 965,4500 985,4520 985,6145 1015,6175 1130,6175 1150,6175
  Bottom Layer w15: 1150,6175 1225,6175 1250,6150 v1(1250,5975.59)
InputN14: K2N.5 P1.48 | length 3417
  Top Layer w30: K2N.5@1250,6300 v1(1250,6450.59)
  Bottom Layer w9: P1.48@261.81,4550 ccw(c285.95,4574.14) 285.95,4540 336.81,4540 cw(c336.81,4500) 358.01,4533.92 390.61,4516.08 ccw(c411.81,4550) 411.81,4510 ccw(c411.81,4550) 440.1,4521.72 440.1,4521.92 456.46,4538.28 cw(c484.74,4510) 484.74,4550
  Bottom Layer w12: 484.74,4550 940,4550 960,4570 960,6620 990,6650 1130,6650 1150,6650
  Bottom Layer w15: 1150,6650 1225,6650 1250,6625 v1(1250,6450.59)
InputN15: K2O.5 P1.49 | length 3839.6
  Top Layer w30: K2O.5@1250,6775 v1(1250,6925.59)
  Bottom Layer w9: P1.49@186.81,4600 224.74,4600 226.94,4600 cw(c226.94,4494.19) 283.01,4583.92 283.21,4583.81 315.61,4566.08 ccw(c336.81,4600) 336.81,4560 ccw(c336.81,4600) 358.01,4566.08 390.61,4583.92 cw(c411.81,4550) 411.81,4590 424.74,4590 ccw(c424.74,4607.07) 436.81,4595 cw(c448.88,4582.93) 448.88,4600
  Bottom Layer w12: 448.88,4600 915,4600 935,4620 935,6645 1065,6775 1065,7100 1090.79,7125.79 1130,7125.79 1150,7125
  Bottom Layer w15: 1150,7125 1225,7125 1250,7100 v1(1250,6925.59)
InputN16: K2P.5 P1.50 | length 4187.9
  Top Layer w30: K2P.5@1250,7250 v1(1250,7400.59)
  Bottom Layer w9: P1.50@261.81,4650 ccw(c285.95,4674.14) 285.95,4640 336.81,4640 cw(c336.81,4600) 358.01,4633.92 390.61,4616.08 ccw(c411.81,4650) 411.81,4610 ccw(c411.81,4650) 440.1,4621.72 440.1,4621.92 456.46,4638.28 cw(c484.74,4610) 484.74,4650
  Bottom Layer w12: 484.74,4650 890,4650 910,4670 910,6660 1030,6780 1030,6960 1030,7555 1075,7600 1130,7600 1150,7600
  Bottom Layer w15: 1150,7600 1225,7600 1250,7575 v1(1250,7400.59)
InputN17: P1.51 P2.35 | length 3757.4
  Mid-Layer 2 w8: v2@960,6887.52 v2(960,6890)
  Mid-Layer 2 w9: P2.35@186.81,6870 224.74,6870 226.94,6870 cw(c226.94,6764.19) 283.01,6853.92 283.21,6853.81 315.61,6836.08 ccw(c336.81,6870) 336.81,6830 ccw(c336.81,6870) 358.01,6836.08 390.61,6853.92 cw(c411.81,6820) 411.81,6860 424.74,6860 ccw(c424.74,6877.07) 436.81,6865 cw(c448.88,6852.93) 448.88,6870 486.81,6870 505,6870
  Mid-Layer 2 w10: 505,6870 515,6860 927.28,6860 ccw(c927.28,6870) 932.64,6861.55 935.28,6863.23 941.74,6868.19 ccw(c925,6890) 948.39,6875.54 cw(c956.89,6870.27) 949.79,6877.31 958.25,6885.77 ccw(c954.02,6890) v2(960,6890)
  Bottom Layer w8: v2@960,6887.52 v2(960,6890)
  Bottom Layer w9: P1.51@186.81,4700 224.74,4700 226.94,4700 cw(c226.94,4594.19) 283.01,4683.92 283.21,4683.81 315.61,4666.08 ccw(c336.81,4700) 336.81,4660 ccw(c336.81,4700) 358.01,4666.08 390.61,4683.92 cw(c411.81,4650) 411.81,4690 424.74,4690 ccw(c424.74,4707.07) 436.81,4695 cw(c448.88,4682.93) 448.88,4700
  Bottom Layer w10: 895,6860 927.28,6860 ccw(c927.28,6870) 932.64,6861.55 935.28,6863.23 941.74,6868.19 ccw(c925,6890) 948.39,6875.54 cw(c956.89,6870.27) 949.79,6877.31 958.25,6885.77 ccw(c954.02,6890) v2(960,6890)
  Bottom Layer w12: 448.88,4700 865,4700 885,4720 885,6846.81 ; 885,6850 895,6860
InputN18: P1.52 P2.36 | length 3566.4
  Mid-Layer 2 w8: v2@935,6937.52 v2(935,6940)
  Mid-Layer 2 w9: P2.36@261.81,6920 ccw(c285.95,6944.14) 285.95,6910 336.81,6910 cw(c336.81,6870) 358.01,6903.92 390.61,6886.08 ccw(c411.81,6920) 411.81,6880 ccw(c411.81,6920) 440.1,6891.72 440.1,6891.92 456.46,6908.28 cw(c484.74,6880) 484.74,6920 486.81,6920 505,6920
  Mid-Layer 2 w10: 505,6920 515,6910 902.28,6910 ccw(c902.28,6920) 907.64,6911.55 910.28,6913.23 916.74,6918.19 ccw(c900,6940) 923.39,6925.54 cw(c931.89,6920.27) 924.79,6927.31 933.25,6935.77 ccw(c929.02,6940) v2(935,6940)
  Bottom Layer w8: v2@935,6937.52 v2(935,6940)
  Bottom Layer w9: P1.52@261.81,4750 ccw(c285.95,4774.14) 285.95,4740 336.81,4740 cw(c336.81,4700) 358.01,4733.92 390.61,4716.08 ccw(c411.81,4750) 411.81,4710 ccw(c411.81,4750) 440.1,4721.72 440.1,4721.92 456.46,4738.28 cw(c484.74,4710) 484.74,4750
  Bottom Layer w10: 870,6910 902.28,6910 ccw(c902.28,6920) 907.64,6911.55 910.28,6913.23 916.74,6918.19 ccw(c900,6940) 923.39,6925.54 cw(c931.89,6920.27) 924.79,6927.31 933.25,6935.77 ccw(c929.02,6940) v2(935,6940)
  Bottom Layer w12: 484.74,4750 840,4750 860,4770 860,6896.81 ; 860,6900 870,6910
InputN19: P1.53 P2.37 | length 3657.4
  Mid-Layer 2 w8: v2@910,6987.52 v2(910,6990)
  Mid-Layer 2 w9: P2.37@186.81,6970 224.74,6970 226.94,6970 cw(c226.94,6864.19) 283.01,6953.92 283.21,6953.81 315.61,6936.08 ccw(c336.81,6970) 336.81,6930 ccw(c336.81,6970) 358.01,6936.08 390.61,6953.92 cw(c411.81,6920) 411.81,6960 424.74,6960 ccw(c424.74,6977.07) 436.81,6965 cw(c448.88,6952.93) 448.88,6970 486.81,6970 505,6970
  Mid-Layer 2 w10: 505,6970 515,6960 877.28,6960 ccw(c877.28,6970) 882.64,6961.55 885.28,6963.23 891.74,6968.19 ccw(c875,6990) 898.39,6975.54 cw(c906.89,6970.27) 899.79,6977.31 908.25,6985.77 ccw(c904.02,6990) v2(910,6990)
  Bottom Layer w8: v2@910,6987.52 v2(910,6990)
  Bottom Layer w9: P1.53@186.81,4800 224.74,4800 226.94,4800 cw(c226.94,4694.19) 283.01,4783.92 283.21,4783.81 315.61,4766.08 ccw(c336.81,4800) 336.81,4760 ccw(c336.81,4800) 358.01,4766.08 390.61,4783.92 cw(c411.81,4750) 411.81,4790 424.74,4790 ccw(c424.74,4807.07) 436.81,4795 cw(c448.88,4782.93) 448.88,4800
  Bottom Layer w10: 845,6960 877.28,6960 ccw(c877.28,6970) 882.64,6961.55 885.28,6963.23 891.74,6968.19 ccw(c875,6990) 898.39,6975.54 cw(c906.89,6970.27) 899.79,6977.31 908.25,6985.77 ccw(c904.02,6990) v2(910,6990)
  Bottom Layer w12: 448.88,4800 815,4800 835,4820 835,6946.81 ; 835,6950 845,6960
InputN20: P1.54 P2.38 | length 3466.4
  Mid-Layer 2 w8: v2@885,7037.52 v2(885,7040)
  Mid-Layer 2 w9: P2.38@261.81,7020 ccw(c285.95,7044.14) 285.95,7010 336.81,7010 cw(c336.81,6970) 358.01,7003.92 390.61,6986.08 ccw(c411.81,7020) 411.81,6980 ccw(c411.81,7020) 440.1,6991.72 440.1,6991.92 456.46,7008.28 cw(c484.74,6980) 484.74,7020 486.81,7020 505,7020
  Mid-Layer 2 w10: 505,7020 515,7010 852.28,7010 ccw(c852.28,7020) 857.64,7011.55 860.28,7013.23 866.74,7018.19 ccw(c850,7040) 873.39,7025.54 cw(c881.89,7020.27) 874.79,7027.31 883.25,7035.77 ccw(c879.02,7040) v2(885,7040)
  Bottom Layer w8: v2@885,7037.52 v2(885,7040)
  Bottom Layer w9: P1.54@261.81,4850 ccw(c285.95,4874.14) 285.95,4840 336.81,4840 cw(c336.81,4800) 358.01,4833.92 390.61,4816.08 ccw(c411.81,4850) 411.81,4810 ccw(c411.81,4850) 440.1,4821.72 440.1,4821.92 456.46,4838.28 cw(c484.74,4810) 484.74,4850
  Bottom Layer w10: 820,7010 852.28,7010 ccw(c852.28,7020) 857.64,7011.55 860.28,7013.23 866.74,7018.19 ccw(c850,7040) 873.39,7025.54 cw(c881.89,7020.27) 874.79,7027.31 883.25,7035.77 ccw(c879.02,7040) v2(885,7040)
  Bottom Layer w12: 484.74,4850 790,4850 810,4870 810,6996.81 ; 810,7000 820,7010
InputN21: P1.55 P2.39 | length 3557.4
  Mid-Layer 2 w8: v2@860,7087.52 v2(860,7090)
  Mid-Layer 2 w9: P2.39@186.81,7070 224.74,7070 226.94,7070 cw(c226.94,6964.19) 283.01,7053.92 283.21,7053.81 315.61,7036.08 ccw(c336.81,7070) 336.81,7030 ccw(c336.81,7070) 358.01,7036.08 390.61,7053.92 cw(c411.81,7020) 411.81,7060 424.74,7060 ccw(c424.74,7077.07) 436.81,7065 cw(c448.88,7052.93) 448.88,7070 486.81,7070 505,7070
  Mid-Layer 2 w10: 505,7070 515,7060 827.28,7060 ccw(c827.28,7070) 832.64,7061.55 835.28,7063.23 841.74,7068.19 ccw(c825,7090) 848.39,7075.54 cw(c856.89,7070.27) 849.79,7077.31 858.25,7085.77 ccw(c854.02,7090) v2(860,7090)
  Bottom Layer w8: v2@860,7087.52 v2(860,7090)
  Bottom Layer w9: P1.55@186.81,4900 224.74,4900 226.94,4900 cw(c226.94,4794.19) 283.01,4883.92 283.21,4883.81 315.61,4866.08 ccw(c336.81,4900) 336.81,4860 ccw(c336.81,4900) 358.01,4866.08 390.61,4883.92 cw(c411.81,4850) 411.81,4890 424.74,4890 ccw(c424.74,4907.07) 436.81,4895 cw(c448.88,4882.93) 448.88,4900
  Bottom Layer w10: 795,7060 827.28,7060 ccw(c827.28,7070) 832.64,7061.55 835.28,7063.23 841.74,7068.19 ccw(c825,7090) 848.39,7075.54 cw(c856.89,7070.27) 849.79,7077.31 858.25,7085.77 ccw(c854.02,7090) v2(860,7090)
  Bottom Layer w12: 448.88,4900 765,4900 785,4920 785,7046.81 ; 785,7050 795,7060
InputN22: P1.56 P2.40 | length 3366.4
  Mid-Layer 2 w8: v2@835,7137.52 v2(835,7140)
  Mid-Layer 2 w9: P2.40@261.81,7120 ccw(c285.95,7144.14) 285.95,7110 336.81,7110 cw(c336.81,7070) 358.01,7103.92 390.61,7086.08 ccw(c411.81,7120) 411.81,7080 ccw(c411.81,7120) 440.1,7091.72 440.1,7091.92 456.46,7108.28 cw(c484.74,7080) 484.74,7120 486.81,7120 505,7120
  Mid-Layer 2 w10: 505,7120 515,7110 802.28,7110 ccw(c802.28,7120) 807.64,7111.55 810.28,7113.23 816.74,7118.19 ccw(c800,7140) 823.39,7125.54 cw(c831.89,7120.27) 824.79,7127.31 833.25,7135.77 ccw(c829.02,7140) v2(835,7140)
  Bottom Layer w8: v2@835,7137.52 v2(835,7140)
  Bottom Layer w9: P1.56@261.81,4950 ccw(c285.95,4974.14) 285.95,4940 336.81,4940 cw(c336.81,4900) 358.01,4933.92 390.61,4916.08 ccw(c411.81,4950) 411.81,4910 ccw(c411.81,4950) 440.1,4921.72 440.1,4921.92 456.46,4938.28 cw(c484.74,4910) 484.74,4950
  Bottom Layer w10: 770,7110 802.28,7110 ccw(c802.28,7120) 807.64,7111.55 810.28,7113.23 816.74,7118.19 ccw(c800,7140) 823.39,7125.54 cw(c831.89,7120.27) 824.79,7127.31 833.25,7135.77 ccw(c829.02,7140) v2(835,7140)
  Bottom Layer w12: 484.74,4950 740,4950 760,4970 760,7096.81 ; 760,7100 770,7110
InputN23: P1.57 P2.41 | length 3457.4
  Mid-Layer 2 w8: v2@810,7187.52 v2(810,7190)
  Mid-Layer 2 w9: P2.41@186.81,7170 224.74,7170 226.94,7170 cw(c226.94,7064.19) 283.01,7153.92 283.21,7153.81 315.61,7136.08 ccw(c336.81,7170) 336.81,7130 ccw(c336.81,7170) 358.01,7136.08 390.61,7153.92 cw(c411.81,7120) 411.81,7160 424.74,7160 ccw(c424.74,7177.07) 436.81,7165 cw(c448.88,7152.93) 448.88,7170 486.81,7170 505,7170
  Mid-Layer 2 w10: 505,7170 515,7160 777.28,7160 ccw(c777.28,7170) 782.64,7161.55 785.28,7163.23 791.74,7168.19 ccw(c775,7190) 798.39,7175.54 cw(c806.89,7170.27) 799.79,7177.31 808.25,7185.77 ccw(c804.02,7190) v2(810,7190)
  Bottom Layer w8: v2@810,7187.52 v2(810,7190)
  Bottom Layer w9: P1.57@186.81,5000 224.74,5000 226.94,5000 cw(c226.94,4894.19) 283.01,4983.92 283.21,4983.81 315.61,4966.08 ccw(c336.81,5000) 336.81,4960 ccw(c336.81,5000) 358.01,4966.08 390.61,4983.92 cw(c411.81,4950) 411.81,4990 424.74,4990 ccw(c424.74,5007.07) 436.81,4995 cw(c448.88,4982.93) 448.88,5000
  Bottom Layer w10: 745,7160 777.28,7160 ccw(c777.28,7170) 782.64,7161.55 785.28,7163.23 791.74,7168.19 ccw(c775,7190) 798.39,7175.54 cw(c806.89,7170.27) 799.79,7177.31 808.25,7185.77 ccw(c804.02,7190) v2(810,7190)
  Bottom Layer w12: 448.88,5000 715,5000 735,5020 735,7146.81 ; 735,7150 745,7160
InputN24: P1.58 P2.42 | length 3266.4
  Mid-Layer 2 w8: v2@785,7237.52 v2(785,7240)
  Mid-Layer 2 w9: P2.42@261.81,7220 ccw(c285.95,7244.14) 285.95,7210 336.81,7210 cw(c336.81,7170) 358.01,7203.92 390.61,7186.08 ccw(c411.81,7220) 411.81,7180 ccw(c411.81,7220) 440.1,7191.72 440.1,7191.92 456.46,7208.28 cw(c484.74,7180) 484.74,7220 486.81,7220 505,7220
  Mid-Layer 2 w10: 505,7220 515,7210 752.28,7210 ccw(c752.28,7220) 757.64,7211.55 760.28,7213.23 766.74,7218.19 ccw(c750,7240) 773.39,7225.54 cw(c781.89,7220.27) 774.79,7227.31 783.25,7235.77 ccw(c779.02,7240) v2(785,7240)
  Bottom Layer w8: v2@785,7237.52 v2(785,7240)
  Bottom Layer w9: P1.58@261.81,5050 ccw(c285.95,5074.14) 285.95,5040 336.81,5040 cw(c336.81,5000) 358.01,5033.92 390.61,5016.08 ccw(c411.81,5050) 411.81,5010 ccw(c411.81,5050) 440.1,5021.72 440.1,5021.92 456.46,5038.28 cw(c484.74,5010) 484.74,5050
  Bottom Layer w10: 720,7210 752.28,7210 ccw(c752.28,7220) 757.64,7211.55 760.28,7213.23 766.74,7218.19 ccw(c750,7240) 773.39,7225.54 cw(c781.89,7220.27) 774.79,7227.31 783.25,7235.77 ccw(c779.02,7240) v2(785,7240)
  Bottom Layer w12: 484.74,5050 690,5050 710,5070 710,7196.81 ; 710,7200 720,7210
